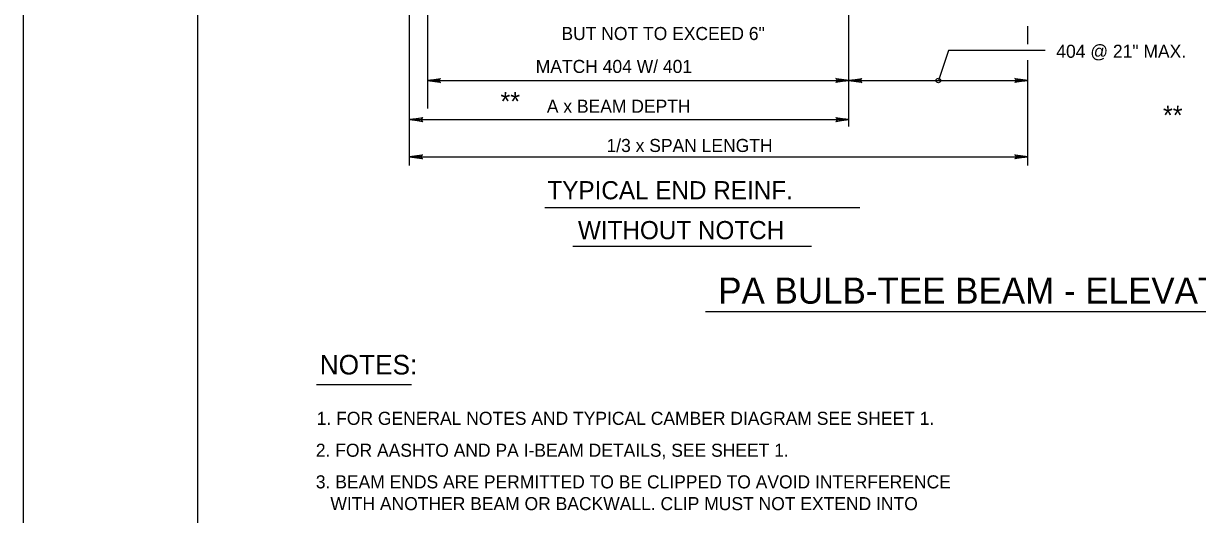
# Model space of a CAD drawing. Extents: x 637933 to 640019, y 298854 to 300042.
# Drawn here: x 637983.9 to 638253.5, y 299146.9 to 299259.7 of the extents above; entities that cross this region are included whole.
import ezdxf

# ---------------------------------------------------------------- set-up
doc = ezdxf.new("R2010")
doc.units = 0
doc.layers.add('1', color=7, linetype='Continuous')
doc.layers.add('PLT-BNDY', color=7, linetype='Continuous')

msp = doc.modelspace()

# ---------------------------------------------------------------- linework, layer by layer
at = {"layer": '1'}
for p, q in [((638023.93, 298869.12), (638023.93, 299433.12)), ((638076.65, 299294.15), (638076.65, 299240.18)), ((638072.53, 299227.1), (638072.53, 299291.6)), ((638173.4, 299236.01), (638173.4, 299276.34)), ((638214.53, 299254.91), (638214.53, 299259.08)), ((638196.27, 299253.52), (638193.96, 299246.6)), ((638218.5, 299253.52), (638196.27, 299253.52)), ((638214.53, 299227.1), (638214.53, 299251.29)), ((638076.65, 299246.6), (638173.4, 299246.6)), ((638173.4, 299246.6), (638214.53, 299246.6)), ((638072.53, 299237.61), (638173.4, 299237.61)), ((638072.53, 299229.08), (638214.53, 299229.08)), ((638175.95, 299217.34), (638103.64, 299217.34)), ((638164.87, 299208.48), (638110.03, 299208.48)), ((638311.88, 299193.49), (638140.49, 299193.49)), ((638051.22, 299176.78), (638072.98, 299176.78))]:
    msp.add_line(p, q, dxfattribs=at)
for points in [[(638079.51, 299246.24), (638079.4, 299246.45), (638076.65, 299246.6), (638079.51, 299246.24), (638079.65, 299246.11), (638076.65, 299246.6), (638079.4, 299246.73), (638079.5, 299246.94), (638076.65, 299246.6), (638079.65, 299247.08), (638079.5, 299246.94)], [(638170.54, 299246.96), (638170.65, 299246.75), (638173.4, 299246.6), (638170.54, 299246.96), (638170.4, 299247.08), (638173.4, 299246.6), (638170.65, 299246.46), (638170.55, 299246.26), (638173.4, 299246.6), (638170.4, 299246.12), (638170.55, 299246.26)], [(638176.25, 299246.24), (638176.15, 299246.45), (638173.4, 299246.6), (638176.25, 299246.24), (638176.4, 299246.11), (638173.4, 299246.6), (638176.14, 299246.73), (638176.24, 299246.94), (638173.4, 299246.6), (638176.4, 299247.08), (638176.24, 299246.94)], [(638211.67, 299246.96), (638211.78, 299246.75), (638214.53, 299246.6), (638211.67, 299246.96), (638211.53, 299247.08), (638214.53, 299246.6), (638211.78, 299246.46), (638211.68, 299246.26), (638214.53, 299246.6), (638211.53, 299246.12), (638211.68, 299246.26)], [(638075.46, 299237.26), (638075.35, 299237.46), (638072.6, 299237.61), (638075.46, 299237.26), (638075.6, 299237.13), (638072.6, 299237.61), (638075.35, 299237.75), (638075.45, 299237.95), (638072.6, 299237.61), (638075.6, 299238.09), (638075.45, 299237.95)], [(638170.54, 299237.97), (638170.65, 299237.77), (638173.4, 299237.61), (638170.54, 299237.97), (638170.4, 299238.1), (638173.4, 299237.61), (638170.65, 299237.48), (638170.55, 299237.28), (638173.4, 299237.61), (638170.4, 299237.14), (638170.55, 299237.28)], [(638075.38, 299228.72), (638075.27, 299228.93), (638072.53, 299229.08), (638075.38, 299228.72), (638075.53, 299228.6), (638072.53, 299229.08), (638075.27, 299229.22), (638075.37, 299229.42), (638072.53, 299229.08), (638075.53, 299229.56), (638075.37, 299229.42)], [(638211.67, 299229.44), (638211.78, 299229.23), (638214.53, 299229.08), (638211.67, 299229.44), (638211.53, 299229.56), (638214.53, 299229.08), (638211.78, 299228.95), (638211.68, 299228.74), (638214.53, 299229.08), (638211.53, 299228.6), (638211.68, 299228.74)]]:
    msp.add_lwpolyline(points, dxfattribs=at)
msp.add_circle((638193.96, 299246.6), 0.51, dxfattribs=at)
at = {"layer": 'PLT-BNDY'}
msp.add_lwpolyline([(637983.93, 299448.12), (638824.93, 299448.12), (638824.93, 298854.12), (637983.93, 298854.12)], close=True, dxfattribs=at)

# ---------------------------------------------------------------- texts
at = {"layer": '1'}
for s, height, p in [('BUT NOT TO EXCEED 6"', 3, (638107.44, 299255.89)), ('404 @ 21" MAX.', 3, (638221.04, 299251.81)), ('MATCH 404 W/ 401', 3, (638101.53, 299248.33)), ('**', 4.32, (638093.44, 299239.66)), ('A x BEAM DEPTH', 3, (638104.08, 299239.19)), ('**', 4.32, (638245.53, 299236.48)), ('1/3 x SPAN LENGTH', 3, (638117.78, 299230.18)), ('TYPICAL END REINF.', 4.1665, (638104.21, 299219.32)), ('WITHOUT NOTCH', 4.1665, (638111.22, 299210.16)), ('PA BULB-TEE BEAM - ELEVATION', 6, (638143.43, 299195.35)), ('NOTES:', 4.5, (638051.95, 299179.09)), ('1. FOR GENERAL NOTES AND TYPICAL CAMBER DIAGRAM SEE SHEET 1.', 3, (638051.25, 299167.52)), ('2. FOR AASHTO AND PA I-BEAM DETAILS, SEE SHEET 1.', 3, (638051.05, 299160.19)), ('3. BEAM ENDS ARE PERMITTED TO BE CLIPPED TO AVOID INTERFERENCE', 3, (638051.05, 299152.93)), ('   WITH ANOTHER BEAM OR BACKWALL. CLIP MUST NOT EXTEND INTO', 3, (638051.05, 299147.93))]:
    msp.add_text(s, height=height, dxfattribs=at).set_placement(p)

doc.saveas('drawing.dxf')
